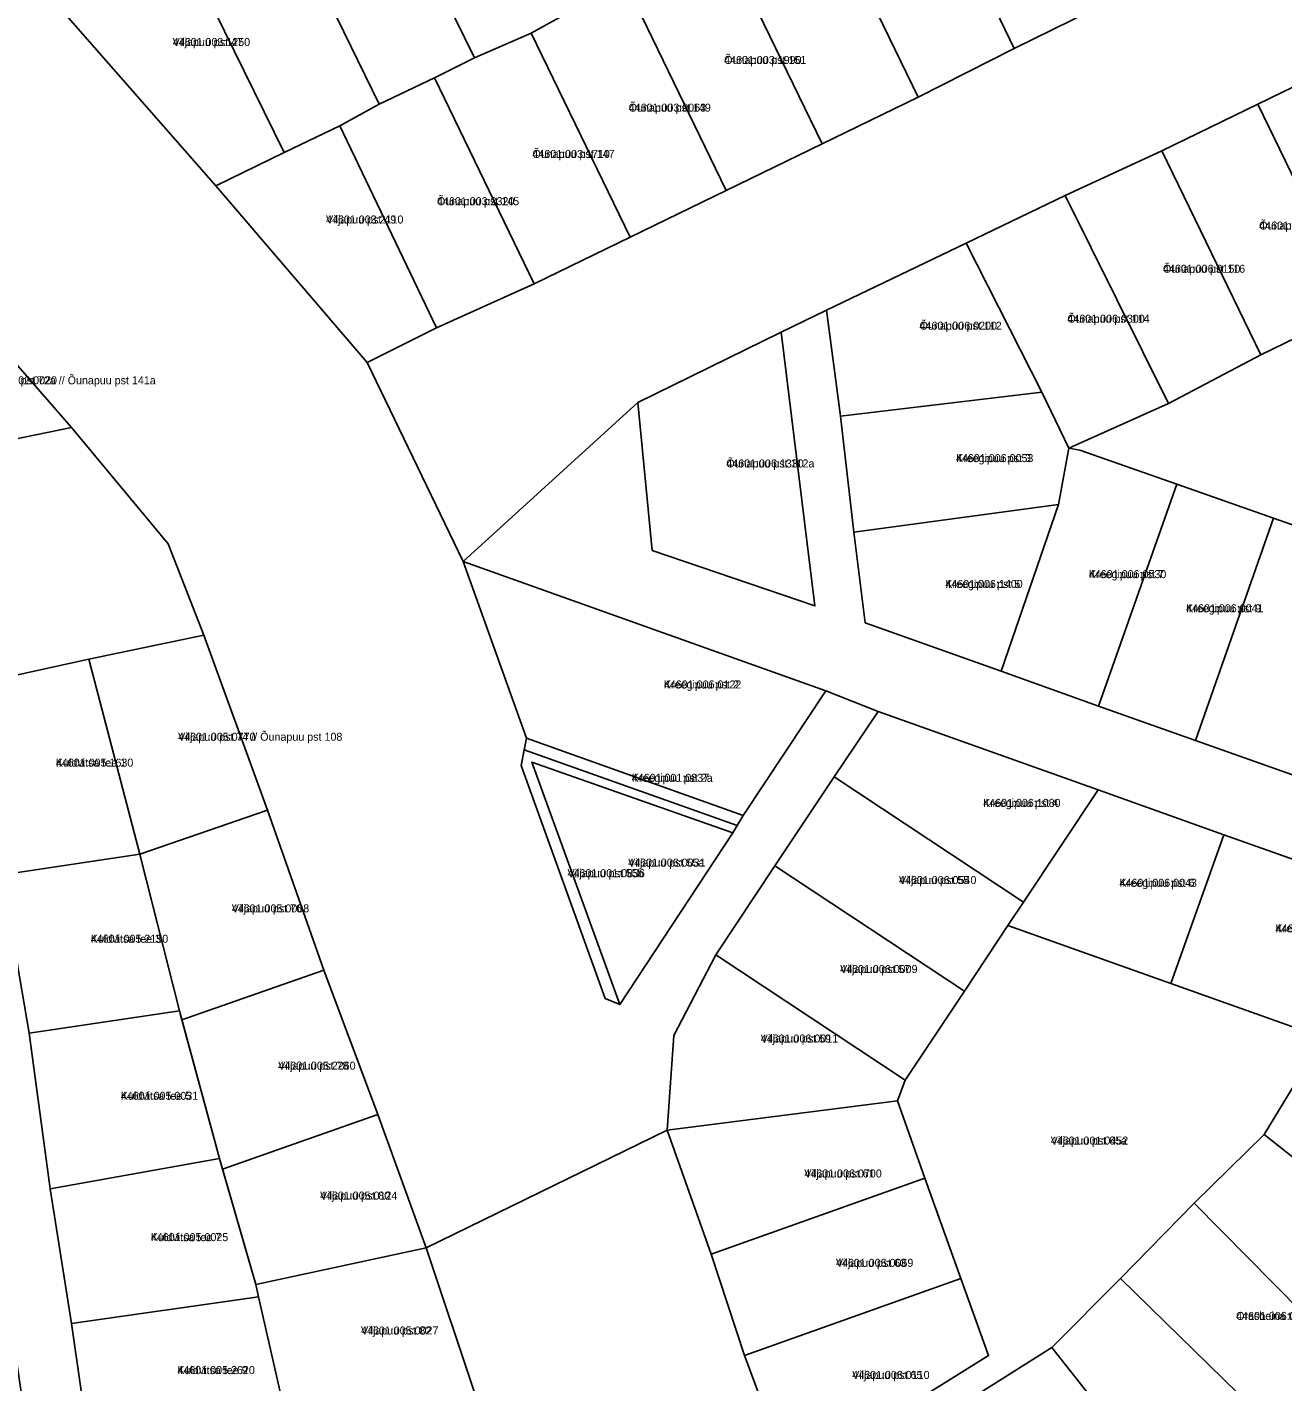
# Model space of a CAD drawing. Extents: x 551843 to 558501, y 6589003 to 6595718.
# Drawn here: x 553484 to 553719.3, y 6593051.3 to 6593305.2 of the extents above; entities that cross this region are included whole.
import ezdxf

# ---------------------------------------------------------------- set-up
doc = ezdxf.new("R2010")
doc.units = 0
for name, color, linetype in [('L_AADRESS', 7, 'Continuous'), ('PIIR', 7, 'Continuous'), ('TUNNUS', 7, 'Continuous')]:
    doc.layers.add(name, color=color, linetype=linetype)

msp = doc.modelspace()

# ---------------------------------------------------------------- linework, layer by layer
at = {"layer": 'PIIR'}
for points in [[(553687.05, 6593310.03), (553668.98, 6593301.15), (553650.49, 6593339.52), (553659.1, 6593343.53), (553667.94, 6593347.67)], [(553549.16, 6593337.48), (553567.31, 6593346.37), (553585.88, 6593308.19), (553578.47, 6593304.06), (553567.84, 6593299.41)], [(553549.16, 6593337.48), (553567.84, 6593299.41), (553560.38, 6593295.66), (553549.99, 6593290.73), (553531.41, 6593328.81)], [(553651.02, 6593292.07), (553632.44, 6593330.3), (553642.31, 6593335.12), (553650.49, 6593339.52), (553668.98, 6593301.15)], [(553632.44, 6593330.3), (553651.02, 6593292.07), (553633.02, 6593283.31), (553614.45, 6593321.56), (553625.2, 6593326.78)], [(553513.49, 6593319.73), (553531.41, 6593328.81), (553549.99, 6593290.73), (553542.61, 6593286.7), (553532.21, 6593281.68)], [(553490.4, 6593308.49), (553513.49, 6593319.73), (553532.21, 6593281.68), (553519.35, 6593275.42)], [(553596.25, 6593313.31), (553603.76, 6593317.01), (553614.45, 6593321.56), (553633.02, 6593283.31), (553615.03, 6593274.57)], [(553597.04, 6593265.82), (553578.47, 6593304.06), (553585.88, 6593308.19), (553596.25, 6593313.31), (553615.03, 6593274.57)], [(553560.38, 6593295.66), (553567.84, 6593299.41), (553578.47, 6593304.06), (553597.04, 6593265.82), (553579.05, 6593257.07)], [(553714.63, 6593290.73), (553732.62, 6593299.48), (553751.19, 6593261.25), (553733.19, 6593252.5)], [(553542.61, 6593286.7), (553549.99, 6593290.73), (553560.38, 6593295.66), (553579.05, 6593257.07), (553560.71, 6593248.86)], [(553696.64, 6593281.99), (553714.63, 6593290.73), (553733.19, 6593252.5), (553715.21, 6593243.76)], [(553532.21, 6593281.68), (553542.61, 6593286.7), (553560.71, 6593248.86), (553547.73, 6593242.35), (553519.35, 6593275.42)], [(553696.64, 6593281.99), (553715.21, 6593243.76), (553697.93, 6593234.65), (553678.52, 6593273.63)], [(553659.99, 6593264.68), (553678.52, 6593273.63), (553697.93, 6593234.65), (553679.24, 6593226.27), (553674.15, 6593236.81)], [(553492.32, 6593230.16), (553463.41, 6593224.22), (553458.6, 6593263.38), (553457.9, 6593269.64)], [(553659.99, 6593264.68), (553674.15, 6593236.81), (553636.41, 6593232.3), (553633.83, 6593252.18)], [(553625.34, 6593248.02), (553631.64, 6593196.72), (553601.15, 6593207.13), (553598.43, 6593234.84)], [(553674.15, 6593236.81), (553679.24, 6593226.27), (553677.3, 6593215.72), (553638.92, 6593210.56), (553636.41, 6593232.3)], [(553677.3, 6593215.72), (553679.24, 6593226.27), (553681.32, 6593225.9), (553699.45, 6593219.57), (553684.8, 6593177.92), (553666.53, 6593184.48)], [(553702.95, 6593171.53), (553684.8, 6593177.92), (553699.45, 6593219.57), (553717.61, 6593213.17)], [(553677.3, 6593215.72), (553666.53, 6593184.48), (553641.09, 6593193.54), (553638.92, 6593210.56)], [(553717.61, 6593213.17), (553735.8, 6593206.72), (553721.14, 6593165.08), (553702.95, 6593171.53)], [(553565.74, 6593205.06), (553633.67, 6593180.83), (553618.19, 6593157.49), (553577.62, 6593171.96)], [(553517.12, 6593191.24), (553529.05, 6593158.49), (553505.14, 6593150.22), (553495.57, 6593186.73)], [(553505.14, 6593150.22), (553479.34, 6593146.36), (553473.68, 6593181.93), (553495.57, 6593186.73)], [(553643.5, 6593176.94), (553684.71, 6593162.25), (553670.71, 6593141.21), (553635.28, 6593164.7)], [(553592.35, 6593123.17), (553576.61, 6593166.86), (553577.19, 6593169.78), (553617.07, 6593155.59), (553616.24, 6593154.19), (553578.58, 6593167.44), (553595.1, 6593122.04)], [(553577.19, 6593169.78), (553577.62, 6593171.96), (553618.19, 6593157.49), (553617.07, 6593155.59)], [(553578.58, 6593167.44), (553616.24, 6593154.19), (553595.1, 6593122.04)], [(553635.28, 6593164.7), (553670.71, 6593141.21), (553667.82, 6593136.86), (553659.67, 6593124.55), (553624.12, 6593148.01)], [(553670.71, 6593141.21), (553684.71, 6593162.25), (553708.29, 6593153.86), (553698.37, 6593125.97), (553667.82, 6593136.86)], [(553512.56, 6593120.85), (553505.14, 6593150.22), (553529.05, 6593158.49), (553539.59, 6593128.46), (553513.03, 6593119.18)], [(553708.29, 6593153.86), (553738.79, 6593143.01), (553722.79, 6593117.28), (553698.37, 6593125.97)], [(553505.14, 6593150.22), (553505.29, 6593149.66), (553512.56, 6593120.85), (553484.38, 6593116.68), (553479.34, 6593146.36)], [(553659.67, 6593124.55), (553648.53, 6593107.89), (553613.08, 6593131.35), (553624.12, 6593148.01)], [(553667.82, 6593136.86), (553698.37, 6593125.97), (553722.79, 6593117.28), (553724.65, 6593112.16), (553715.84, 6593097.69), (553702.72, 6593084.85), (553688.9, 6593070.71), (553676.07, 6593057.76), (553659.09, 6593047.13), (553642.16, 6593036.49), (553629.16, 6593028.32), (553627.05, 6593033.11), (553664.19, 6593056.27), (553658.97, 6593070.69), (553652.27, 6593089.53), (553647.12, 6593103.99), (553648.53, 6593107.89), (553659.67, 6593124.55)], [(553648.53, 6593107.89), (553647.12, 6593103.99), (553603.96, 6593098.5), (553605.2, 6593116.22), (553613.08, 6593131.35)], [(553539.59, 6593128.46), (553549.73, 6593101.43), (553520.63, 6593091.22), (553520.07, 6593093.17), (553513.03, 6593119.18)], [(553512.56, 6593120.85), (553520.07, 6593093.17), (553488.36, 6593087.54), (553484.38, 6593116.68)], [(553715.84, 6593097.69), (553724.65, 6593112.16), (553761.14, 6593089.7), (553749.62, 6593070.96)], [(553603.96, 6593098.5), (553647.12, 6593103.99), (553652.27, 6593089.53), (553612.22, 6593075.29)], [(553549.73, 6593101.43), (553558.81, 6593076.48), (553526.86, 6593069.58), (553520.63, 6593091.22)], [(553702.72, 6593084.85), (553715.84, 6593097.69), (553749.62, 6593070.96), (553732.87, 6593054.27)], [(553520.07, 6593093.17), (553526.86, 6593069.58), (553527.35, 6593067.27), (553492.34, 6593062.25), (553488.36, 6593087.54)], [(553612.22, 6593075.29), (553652.27, 6593089.53), (553658.97, 6593070.69), (553618.46, 6593056.27)], [(553719.27, 6593041.04), (553688.9, 6593070.71), (553702.72, 6593084.85), (553732.87, 6593054.27)], [(553527.35, 6593067.27), (553526.86, 6593069.58), (553558.81, 6593076.48), (553567.96, 6593048.97), (553532.7, 6593043.96)], [(553658.97, 6593070.69), (553664.19, 6593056.27), (553627.05, 6593033.11), (553618.46, 6593056.27)], [(553688.9, 6593070.71), (553719.27, 6593041.04), (553702.17, 6593024.66), (553676.07, 6593057.76)], [(553492.34, 6593062.25), (553527.35, 6593067.27), (553532.7, 6593043.96), (553495.75, 6593038.34)], [(553676.07, 6593057.76), (553702.17, 6593024.66), (553681.43, 6593011.49), (553659.09, 6593047.13)]]:
    msp.add_lwpolyline(points, close=True, dxfattribs=at)
for points in [[(553732.62, 6593299.48), (553714.63, 6593290.73), (553696.64, 6593281.99), (553678.52, 6593273.63), (553659.99, 6593264.68), (553633.83, 6593252.18), (553625.34, 6593248.02), (553598.43, 6593234.84), (553565.74, 6593205.06), (553547.73, 6593242.35), (553560.71, 6593248.86), (553579.05, 6593257.07), (553597.04, 6593265.82), (553615.03, 6593274.57), (553633.02, 6593283.31), (553651.02, 6593292.07), (553668.98, 6593301.15), (553687.05, 6593310.03), (553695.53, 6593313.71), (553717.06, 6593324.38), (553739.43, 6593335.04)], [(553490.4, 6593308.49), (553519.35, 6593275.42), (553547.73, 6593242.35), (553565.74, 6593205.06), (553577.62, 6593171.96), (553576.61, 6593166.86), (553592.35, 6593123.17), (553595.1, 6593122.04), (553616.24, 6593154.19), (553617.07, 6593155.59), (553618.19, 6593157.49), (553633.67, 6593180.83), (553643.5, 6593176.94), (553635.28, 6593164.7), (553624.12, 6593148.01), (553613.08, 6593131.35), (553605.2, 6593116.22), (553603.96, 6593098.5), (553558.81, 6593076.48), (553549.73, 6593101.43), (553539.59, 6593128.46), (553529.05, 6593158.49), (553517.12, 6593191.24), (553510.47, 6593208.37), (553492.32, 6593230.16), (553457.9, 6593269.64)], [(553738.79, 6593143.01), (553708.29, 6593153.86), (553684.71, 6593162.25), (553643.5, 6593176.94), (553633.67, 6593180.83), (553565.74, 6593205.06), (553598.43, 6593234.84), (553601.15, 6593207.13), (553631.64, 6593196.72), (553625.34, 6593248.02), (553633.83, 6593252.18), (553636.41, 6593232.3), (553638.92, 6593210.56), (553641.09, 6593193.54), (553666.53, 6593184.48), (553684.8, 6593177.92), (553702.95, 6593171.53), (553721.14, 6593165.08)], [(553735.8, 6593206.72), (553717.61, 6593213.17), (553699.45, 6593219.57), (553681.32, 6593225.9), (553679.24, 6593226.27), (553697.93, 6593234.65), (553715.21, 6593243.76), (553733.19, 6593252.5)], [(553463.41, 6593224.22), (553492.32, 6593230.16), (553510.47, 6593208.37), (553517.12, 6593191.24), (553495.57, 6593186.73), (553473.68, 6593181.93)], [(553483.64, 6593044.41), (553480.36, 6593066.71), (553476.88, 6593089.24), (553473.4, 6593111.59), (553469.91, 6593133.75), (553466.25, 6593156.6), (553462.17, 6593182.27), (553473.68, 6593181.93), (553479.34, 6593146.36), (553484.38, 6593116.68), (553488.36, 6593087.54), (553492.34, 6593062.25), (553495.75, 6593038.34)], [(553567.96, 6593048.97), (553558.81, 6593076.48), (553603.96, 6593098.5), (553612.22, 6593075.29), (553618.46, 6593056.27), (553627.05, 6593033.11)]]:
    msp.add_lwpolyline(points, dxfattribs=at)

# ---------------------------------------------------------------- texts
at = {"layer": 'L_AADRESS'}
for s, p in [('Viljapuu pst 47', (553511.3, 6593301.64)), ('Õunapuu pst 151', (553614.64, 6593298.28)), ('Õunapuu pst 149', (553596.75, 6593289.35)), ('Õunapuu pst 147', (553578.71, 6593280.67)), ('Õunapuu pst 145', (553560.83, 6593271.82)), ('Viljapuu pst 49', (553540.03, 6593268.39)), ('Õunapuu pst 118', (553714.91, 6593267.26)), ('Õunapuu pst 116', (553696.87, 6593259.16)), ('Õunapuu pst 114', (553678.96, 6593249.8)), ('Õunapuu pst 112', (553651.26, 6593248.49)), ('Viljapuu pst 72a // Õunapuu pst 141a', (553475.11, 6593238.26)), ('Õunapuu pst 112a', (553615.04, 6593222.68)), ('Kreegipuu pst 3', (553658.08, 6593223.68)), ('Kreegipuu pst 7', (553682.99, 6593201.94)), ('Kreegipuu pst 5', (553656.08, 6593200.1)), ('Kreegipuu pst 9', (553701.2, 6593195.55)), ('Kreegipuu pst 2', (553603.35, 6593181.27)), ('Viljapuu pst 74 // Õunapuu pst 108', (553512.31, 6593171.47)), ('Kuldvitsa tee 1', (553489.41, 6593166.62)), ('Kreegipuu pst 2a', (553597.32, 6593163.78)), ('Kreegipuu pst 4', (553663.18, 6593159.08)), ('Viljapuu pst 55a', (553596.64, 6593147.89)), ('Viljapuu pst 55b', (553585.29, 6593145.91)), ('Viljapuu pst 55', (553647.4, 6593144.62)), ('Kreegipuu pst 6', (553688.73, 6593144.11)), ('Viljapuu pst 76', (553522.37, 6593139.31)), ('Kreegipuu pst 8', (553717.97, 6593135.57)), ('Kuldvitsa tee 3', (553495.95, 6593133.62)), ('Viljapuu pst 57', (553636.37, 6593127.95)), ('Viljapuu pst 59', (553621.5, 6593114.93)), ('Viljapuu pst 78', (553531.07, 6593109.84)), ('Kuldvitsa tee 5', (553501.58, 6593104.2)), ('Viljapuu pst 65a', (553675.85, 6593095.81)), ('Viljapuu pst 61', (553629.67, 6593089.64)), ('Viljapuu pst 80', (553538.9, 6593085.5)), ('Kuldvitsa tee 7', (553507.21, 6593077.71)), ('Viljapuu pst 63', (553635.59, 6593072.9)), ('Orasheina tee 79', (553710.58, 6593062.95)), ('Viljapuu pst 82', (553546.59, 6593060.22)), ('Kuldvitsa tee 9', (553512.18, 6593052.8)), ('Viljapuu pst 65', (553638.63, 6593051.9))]:
    msp.add_text(s, height=1.5, dxfattribs=at).set_placement(p)
at = {"layer": 'TUNNUS'}
for s, p in [('44601:003:1250', (553511.3, 6593301.64)), ('44601:003:1990', (553614.64, 6593298.28)), ('44601:003:0063', (553596.75, 6593289.35)), ('44601:003:1710', (553578.71, 6593280.67)), ('44601:003:2320', (553560.83, 6593271.82)), ('44601:003:2110', (553540.03, 6593268.39)), ('44601:006:0550', (553714.91, 6593267.26)), ('44601:006:0150', (553696.87, 6593259.16)), ('44601:006:0300', (553678.96, 6593249.8)), ('44601:006:0200', (553651.26, 6593248.49)), ('44601:002:0020', (553475.11, 6593238.26)), ('44601:006:1330', (553615.04, 6593222.68)), ('44601:006:0053', (553658.08, 6593223.68)), ('44601:006:0530', (553682.99, 6593201.94)), ('44601:006:1400', (553656.08, 6593200.1)), ('44601:006:0041', (553701.2, 6593195.55)), ('44601:006:0122', (553603.35, 6593181.27)), ('44601:005:0770', (553512.31, 6593171.47)), ('44601:005:1630', (553489.41, 6593166.62)), ('44601:001:0837', (553597.32, 6593163.78)), ('44601:006:1080', (553663.18, 6593159.08)), ('44601:006:0031', (553596.64, 6593147.89)), ('44601:001:0836', (553585.29, 6593145.91)), ('44601:006:0540', (553647.4, 6593144.62)), ('44601:006:0043', (553688.73, 6593144.11)), ('44601:005:0008', (553522.37, 6593139.31)), ('44601:006:0003', (553717.97, 6593135.57)), ('44601:005:2150', (553495.95, 6593133.62)), ('44601:006:0009', (553636.37, 6593127.95)), ('44601:006:0011', (553621.5, 6593114.93)), ('44601:005:2260', (553531.07, 6593109.84)), ('44601:005:0031', (553501.58, 6593104.2)), ('44601:001:0452', (553675.85, 6593095.81)), ('44601:006:0700', (553629.67, 6593089.64)), ('44601:005:0124', (553538.9, 6593085.5)), ('44601:005:0025', (553507.21, 6593077.71)), ('44601:006:0069', (553635.59, 6593072.9)), ('44601:006:0310', (553710.58, 6593062.95)), ('44601:005:0027', (553546.59, 6593060.22)), ('44601:005:2620', (553512.18, 6593052.8)), ('44601:006:0110', (553638.63, 6593051.9))]:
    msp.add_text(s, height=1.5, dxfattribs=at).set_placement(p)

doc.saveas('drawing.dxf')
